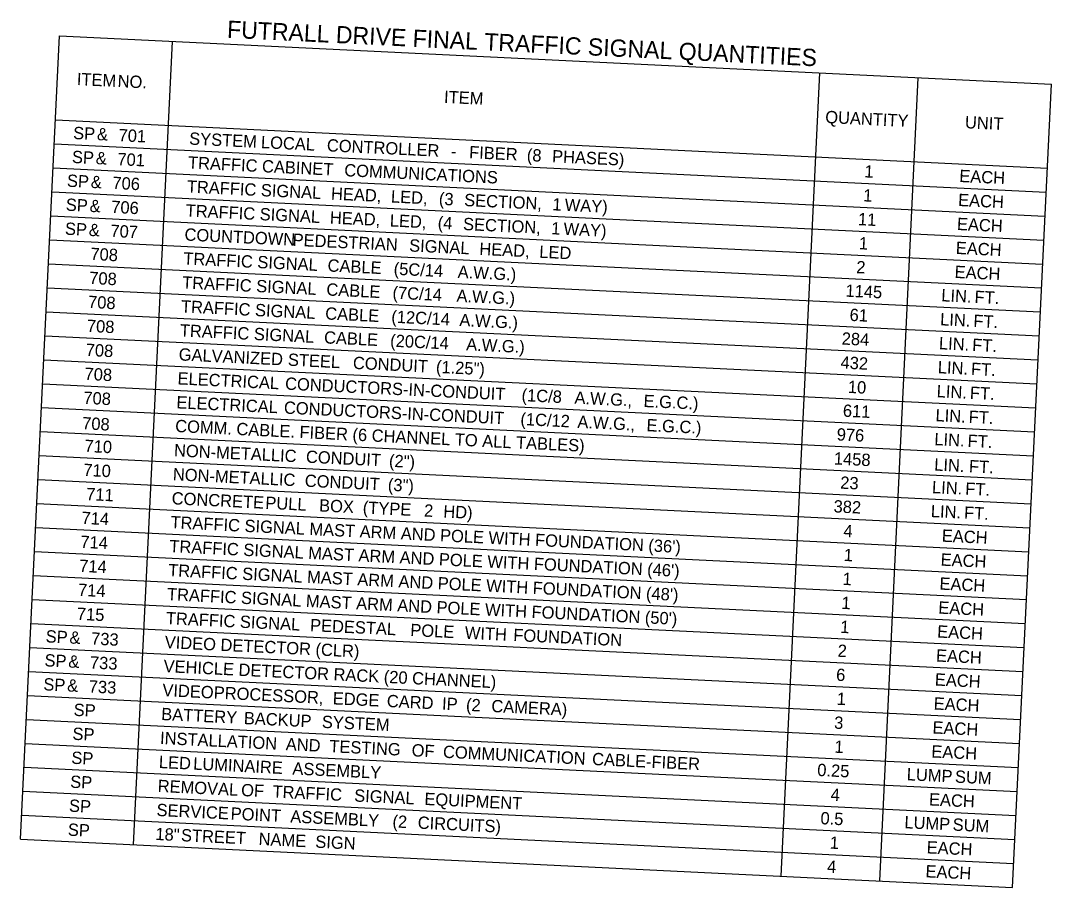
# Model space of a CAD drawing. Extents: x 661030 to 662601, y 642184 to 643065.
# Drawn here: x 661169.4 to 661372.2, y 642806.5 to 642977 of the extents above; entities that cross this region are included whole.
import ezdxf

# ---------------------------------------------------------------- set-up
doc = ezdxf.new("R2010")
doc.units = 0
doc.layers.add('R_Dimension', color=7, linetype='Continuous')

msp = doc.modelspace()

# ---------------------------------------------------------------- linework, layer by layer
at = {"layer": 'R_Dimension'}
for p, q in [((661169.39, 642815.93), (661177.07, 642973.95)), ((661177.07, 642973.95), (661372.16, 642964.47)), ((661191.59, 642814.85), (661199.24, 642972.87)), ((661319.02, 642808.66), (661326.64, 642966.68)), ((661338.39, 642807.72), (661345.98, 642965.74)), ((661364.48, 642806.45), (661372.16, 642964.47)), ((661176.26, 642957.44), (661371.36, 642947.96)), ((661176.04, 642952.72), (661371.13, 642943.25)), ((661175.81, 642948), (661370.9, 642938.53)), ((661175.58, 642943.28), (661370.67, 642933.81)), ((661175.35, 642938.57), (661370.44, 642929.09)), ((661175.12, 642933.85), (661370.21, 642924.38)), ((661174.89, 642929.13), (661369.98, 642919.66)), ((661174.66, 642924.42), (661369.75, 642914.94)), ((661174.43, 642919.7), (661369.52, 642910.23)), ((661174.2, 642914.98), (661369.29, 642905.51)), ((661173.97, 642910.27), (661369.06, 642900.79)), ((661173.97, 642910.27), (661369.06, 642900.79)), ((661173.74, 642905.55), (661368.84, 642896.08)), ((661173.52, 642900.83), (661368.61, 642891.36)), ((661173.29, 642896.11), (661368.38, 642886.64)), ((661173.06, 642891.4), (661368.15, 642881.92)), ((661172.83, 642886.68), (661367.92, 642877.21)), ((661172.6, 642881.96), (661367.69, 642872.49)), ((661172.37, 642877.25), (661367.46, 642867.77)), ((661172.14, 642872.53), (661367.23, 642863.06)), ((661171.91, 642867.81), (661367, 642858.34)), ((661171.68, 642863.1), (661366.77, 642853.62)), ((661171.45, 642858.38), (661366.55, 642848.9)), ((661171.23, 642853.66), (661366.32, 642844.19)), ((661171, 642848.94), (661366.09, 642839.47)), ((661170.77, 642844.23), (661365.86, 642834.75)), ((661170.54, 642839.51), (661365.63, 642830.04)), ((661170.54, 642839.51), (661365.63, 642830.04)), ((661170.31, 642834.79), (661365.4, 642825.32)), ((661170.08, 642830.08), (661365.17, 642820.6)), ((661169.85, 642825.36), (661364.94, 642815.89)), ((661169.62, 642820.64), (661364.71, 642811.17)), ((661169.39, 642815.93), (661364.48, 642806.45)), ((661169.39, 642815.93), (661364.48, 642806.45))]:
    msp.add_line(p, q, dxfattribs=at)

# ---------------------------------------------------------------- texts
for s, height, p in [('FUTRALL DRIVE FINAL TRAFFIC SIGNAL QUANTITIES', 3.3906, (661209.95, 642973.61)), ('ITEM', 2.422, (661180.41, 642964.3)), (' NO.', 2.422, (661187.53, 642963.95)), ('ITEM', 2.422, (661252.64, 642960.79)), ('QUANTITY', 2.422, (661327.63, 642956.84)), ('UNIT', 2.422, (661355.11, 642955.81)), ('SP', 2.422, (661179.68, 642953.69)), (' &', 2.422, (661183.47, 642953.51)), (' 701', 2.422, (661187.72, 642953.3)), ('SYSTEM', 2.422, (661202.51, 642952.59)), (' LOCAL', 2.422, (661215.73, 642951.94)), (' CONTROLLER', 2.4218, (661228.7, 642951.31)), ('SP', 2.422, (661179.45, 642948.98)), (' &', 2.422, (661183.24, 642948.79)), (' 701', 2.422, (661187.49, 642948.59)), (' -', 2.422, (661253.08, 642950.13)), (' FIBER', 2.422, (661256.68, 642949.95)), (' (8', 2.422, (661268.03, 642949.4)), (' PHASES)', 2.422, (661273, 642949.16)), ('TRAFFIC', 2.422, (661202.28, 642947.87)), (' CABINET', 2.422, (661215.93, 642947.2)), (' COMMUNICATIONS', 2.4218, (661232.12, 642946.42)), ('SP', 2.422, (661178.47, 642944.3)), ('1', 2.42, (661335.33, 642946.14)), ('EACH', 2.422, (661354, 642945.23)), (' &', 2.422, (661182.26, 642944.11)), (' 706', 2.422, (661186.51, 642943.91)), ('TRAFFIC', 2.422, (661202.05, 642943.15)), (' SIGNAL', 2.422, (661215.71, 642942.49)), (' HEAD,', 2.422, (661229.51, 642941.82)), (' LED,', 2.422, (661241.3, 642941.24)), (' (3', 2.422, (661250.73, 642940.79)), (' SECTION,', 2.422, (661255.7, 642940.55)), ('1', 2.42, (661335.1, 642941.42)), ('EACH', 2.422, (661353.77, 642940.51)), ('SP', 2.422, (661178.24, 642939.58)), (' &', 2.422, (661182.03, 642939.39)), (' 706', 2.422, (661186.28, 642939.19)), ('TRAFFIC', 2.422, (661201.82, 642938.43)), (' 1', 2.422, (661273.06, 642939.7)), (' WAY)', 2.422, (661275.48, 642939.59)), (' SIGNAL', 2.422, (661215.48, 642937.77)), (' HEAD,', 2.422, (661229.29, 642937.1)), (' LED,', 2.422, (661241.08, 642936.53)), ('11', 2.422, (661334.07, 642936.74)), ('SP', 2.422, (661178.08, 642934.86)), (' &', 2.422, (661181.87, 642934.67)), (' 707', 2.422, (661186.12, 642934.47)), (' (4', 2.422, (661250.5, 642936.07)), (' SECTION,', 2.422, (661255.48, 642935.83)), (' 1', 2.422, (661272.83, 642934.99)), (' WAY)', 2.422, (661275.25, 642934.87)), ('EACH', 2.422, (661353.54, 642935.79)), ('COUNTDOWN', 2.422, (661201.59, 642933.72)), (' PEDESTRIAN', 2.4218, (661221.95, 642932.73)), (' SIGNAL', 2.422, (661244.88, 642931.61)), (' HEAD,', 2.422, (661258.69, 642930.94)), (' LED', 2.422, (661270.48, 642930.37)), ('1', 2.42, (661334.25, 642932)), ('EACH', 2.422, (661353.31, 642931.08)), ('708', 2.422, (661183.08, 642929.89)), ('TRAFFIC', 2.422, (661201.36, 642929)), (' SIGNAL', 2.422, (661215.02, 642928.34)), (' CABLE', 2.422, (661228.83, 642927.67)), (' (5C/14', 2.422, (661241.84, 642927.03)), (' A.W.G.)', 2.422, (661254.43, 642926.42)), ('2', 2.42, (661333.73, 642927.3)), ('EACH', 2.422, (661353.08, 642926.36)), ('708', 2.422, (661182.85, 642925.17)), ('TRAFFIC', 2.422, (661201.13, 642924.28)), (' SIGNAL', 2.422, (661214.79, 642923.62)), (' CABLE', 2.422, (661228.6, 642922.95)), (' (7C/14', 2.422, (661241.61, 642922.32)), ('1145', 2.422, (661331.62, 642922.67)), ('708', 2.422, (661182.62, 642920.45)), (' A.W.G.)', 2.422, (661254.2, 642921.71)), ('LIN.', 2.422, (661350.46, 642921.76)), (' FT.', 2.422, (661356.1, 642921.49)), ('TRAFFIC', 2.422, (661200.9, 642919.57)), (' SIGNAL', 2.422, (661214.56, 642918.9)), (' CABLE', 2.422, (661228.37, 642918.23)), ('61', 2.422, (661332.42, 642917.91)), (' (12C/14', 2.422, (661241.38, 642917.6)), (' A.W.G.)', 2.422, (661254.77, 642916.95)), ('LIN.', 2.422, (661350.23, 642917.04)), (' FT.', 2.422, (661355.87, 642916.77)), ('708', 2.422, (661182.39, 642915.74)), ('TRAFFIC', 2.422, (661200.67, 642914.85)), (' SIGNAL', 2.422, (661214.33, 642914.19)), (' CABLE', 2.422, (661228.14, 642913.52)), (' (20C/14', 2.422, (661241.15, 642912.88)), (' A.W.G.)', 2.422, (661256.1, 642912.16)), ('284', 2.422, (661330.87, 642913.25)), ('LIN.', 2.422, (661350, 642912.33)), (' FT.', 2.422, (661355.64, 642912.05)), ('708', 2.422, (661182.16, 642911.02)), ('GALVANIZED', 2.422, (661200.45, 642910.13)), (' STEEL', 2.422, (661221.03, 642909.13)), (' CONDUIT', 2.422, (661233.82, 642908.51)), (' (1.25")', 2.422, (661250.16, 642907.72)), ('432', 2.422, (661330.64, 642908.54)), ('708', 2.422, (661181.93, 642906.3)), ('LIN.', 2.422, (661349.77, 642907.61)), (' FT.', 2.422, (661355.41, 642907.33)), ('ELECTRICAL', 2.422, (661200.22, 642905.41)), (' CONDUCTORS-IN-CONDUIT', 2.4218, (661220.48, 642904.43)), ('10', 2.422, (661332.08, 642903.74)), (' (1C/8', 2.422, (661267, 642902.17)), ('LIN.', 2.422, (661349.55, 642902.89)), (' FT.', 2.422, (661355.18, 642902.62)), ('708', 2.422, (661181.7, 642901.59)), ('ELECTRICAL', 2.422, (661199.99, 642900.7)), (' CONDUCTORS-IN-CONDUIT', 2.4218, (661220.25, 642899.71)), (' A.W.G.,', 2.422, (661277.41, 642901.67)), (' E.G.C.)', 2.422, (661290.99, 642901.01)), ('611', 2.422, (661331.1, 642899.06)), ('LIN.', 2.422, (661349.32, 642898.17)), (' FT.', 2.422, (661354.95, 642897.9)), ('708', 2.422, (661181.46, 642896.58)), ('COMM. CABLE. FIBER (6 CHANNEL TO ALL TABLES)', 2.4218, (661199.76, 642896.05)), (' (1C/12', 2.422, (661266.77, 642897.46)), (' A.W.G.,', 2.422, (661277.98, 642896.91)), (' E.G.C.)', 2.422, (661291.57, 642896.25)), ('976', 2.422, (661329.89, 642894.39)), ('710', 2.422, (661181.92, 642892.12)), ('LIN.', 2.422, (661349.09, 642893.46)), (' FT.', 2.422, (661354.73, 642893.18)), ('NON-METALLIC', 2.4218, (661199.53, 642891.26)), (' CONDUIT', 2.422, (661224.58, 642890.05)), ('1458', 2.422, (661329.33, 642889.66)), (' (2")', 2.422, (661240.92, 642889.25)), ('LIN. FT.', 2.422, (661349.07, 642888.46)), ('710', 2.422, (661181.69, 642887.4)), ('NON-METALLIC', 2.4218, (661199.3, 642886.55)), (' CONDUIT', 2.422, (661224.35, 642885.33)), (' (3")', 2.422, (661240.69, 642884.54)), ('23', 2.422, (661330.58, 642884.9)), ('LIN.', 2.422, (661348.63, 642884.02)), (' FT.', 2.422, (661354.27, 642883.75)), ('711', 2.422, (661182.25, 642882.65)), ('CONCRETE', 2.422, (661199.07, 642881.83)), (' PULL', 2.422, (661216.59, 642880.98)), (' BOX', 2.422, (661227.17, 642880.47)), (' (TYPE', 2.422, (661235.76, 642880.05)), (' 2', 2.422, (661247.81, 642879.46)), ('382', 2.422, (661329.27, 642880.24)), ('714', 2.422, (661181.34, 642877.96)), (' HD)', 2.422, (661251.6, 642879.28)), ('LIN.', 2.422, (661348.4, 642879.31)), (' FT.', 2.422, (661354.04, 642879.03)), ("TRAFFIC SIGNAL MAST ARM AND POLE WITH FOUNDATION (36')", 2.4218, (661198.84, 642877.11)), ('4', 2.42, (661331.21, 642875.41)), ('EACH', 2.422, (661350.56, 642874.47)), ('714', 2.422, (661181.11, 642873.25)), ("TRAFFIC SIGNAL MAST ARM AND POLE WITH FOUNDATION (46')", 2.4218, (661198.61, 642872.4)), ('1', 2.42, (661331.27, 642870.68)), ('EACH', 2.422, (661350.33, 642869.76)), ('714', 2.422, (661180.88, 642868.53)), ("TRAFFIC SIGNAL MAST ARM AND POLE WITH FOUNDATION (48')", 2.4218, (661198.38, 642867.68)), ('1', 2.42, (661331.04, 642865.97)), ('714', 2.422, (661180.65, 642863.81)), ('EACH', 2.422, (661350.1, 642865.04)), ("TRAFFIC SIGNAL MAST ARM AND POLE WITH FOUNDATION (50')", 2.4218, (661198.15, 642862.96)), ('1', 2.42, (661330.81, 642861.25)), ('715', 2.422, (661180.42, 642859.09)), ('EACH', 2.422, (661349.87, 642860.32)), ('TRAFFIC', 2.422, (661197.93, 642858.24)), (' SIGNAL', 2.422, (661211.58, 642857.58)), (' PEDESTAL', 2.422, (661225.39, 642856.91)), (' POLE', 2.422, (661245.11, 642855.95)), (' WITH', 2.422, (661255.83, 642855.43)), ('1', 2.42, (661330.58, 642856.53)), ('EACH', 2.422, (661349.65, 642855.61)), ('SP', 2.422, (661174.28, 642854.66)), (' &', 2.422, (661178.07, 642854.48)), (' 733', 2.422, (661182.32, 642854.27)), ('VIDEO DETECTOR (CLR)', 2.4218, (661197.7, 642853.53)), (' FOUNDATION', 2.4218, (661265.37, 642854.97)), ('2', 2.42, (661330.07, 642851.83)), ('SP', 2.422, (661174.05, 642849.95)), (' &', 2.422, (661177.84, 642849.76)), (' 733', 2.422, (661182.09, 642849.56)), ('EACH', 2.422, (661349.42, 642850.89)), ('VEHICLE DETECTOR RACK (20 CHANNEL)', 2.4218, (661197.47, 642848.81)), ('6', 2.42, (661329.77, 642847.11)), ('SP', 2.422, (661173.82, 642845.23)), (' &', 2.422, (661177.61, 642845.05)), ('EACH', 2.422, (661349.19, 642846.17)), (' 733', 2.422, (661181.86, 642844.84)), ('VIDEO', 2.422, (661197.24, 642844.09)), (' PROCESSOR,', 2.4218, (661206.44, 642843.65)), (' EDGE', 2.422, (661229.85, 642842.51)), (' CARD', 2.422, (661240.49, 642841.99)), (' IP', 2.422, (661251.35, 642841.47)), (' (2', 2.422, (661256.07, 642841.24)), (' CAMERA)', 2.422, (661261.05, 642841)), ('1', 2.42, (661329.89, 642842.38)), ('EACH', 2.422, (661348.96, 642841.45)), ('SP', 2.422, (661179.78, 642840.21)), ('BATTERY', 2.422, (661197.01, 642839.38)), (' BACKUP', 2.422, (661212.36, 642838.63)), (' SYSTEM', 2.422, (661227.71, 642837.89)), ('3', 2.42, (661329.38, 642837.68)), ('SP', 2.422, (661179.55, 642835.5)), ('EACH', 2.422, (661348.73, 642836.74)), ('INSTALLATION', 2.4218, (661196.78, 642834.66)), (' AND', 2.422, (661220.61, 642833.5)), (' TESTING', 2.422, (661229.18, 642833.09)), ('1', 2.42, (661329.44, 642832.95)), ('SP', 2.422, (661179.33, 642830.78)), (' OF', 2.422, (661245.37, 642832.3)), (' COMMUNICATION', 2.4218, (661251.54, 642832)), ('EACH', 2.422, (661348.5, 642832.02)), ('LED', 2.422, (661196.55, 642829.94)), (' LUMINAIRE', 2.422, (661202.4, 642829.66)), (' CABLE-FIBER', 2.4218, (661280.87, 642830.58)), (' ASSEMBLY', 2.422, (661221.92, 642828.71)), ('0.25', 2.422, (661326.06, 642828.38)), ('LUMP', 2.422, (661343.66, 642827.53)), (' SUM', 2.422, (661352.25, 642827.11)), ('SP', 2.422, (661179.1, 642826.06)), ('REMOVAL', 2.422, (661196.32, 642825.23)), (' OF', 2.422, (661211.83, 642824.47)), (' TRAFFIC', 2.422, (661218, 642824.17)), (' SIGNAL', 2.422, (661234.07, 642823.39)), (' EQUIPMENT', 2.422, (661247.88, 642822.72)), ('4', 2.42, (661328.69, 642823.53)), ('SP', 2.422, (661178.87, 642821.35)), ('EACH', 2.422, (661348.04, 642822.59)), ('SERVICE', 2.422, (661196.09, 642820.51)), (' POINT', 2.422, (661209.77, 642819.84)), (' ASSEMBLY', 2.422, (661221.5, 642819.27)), ('0.5', 2.422, (661326.69, 642818.89)), ('SP', 2.422, (661178.64, 642816.63)), (' (2', 2.422, (661241.6, 642818.3)), (' CIRCUITS)', 2.422, (661246.57, 642818.06)), ('LUMP', 2.422, (661343.2, 642818.09)), (' SUM', 2.422, (661351.79, 642817.68)), ('18"', 2.422, (661195.86, 642815.79)), (' STREET', 2.422, (661200, 642815.59)), (' NAME', 2.422, (661215.27, 642814.85)), (' SIGN', 2.422, (661226.42, 642814.31)), ('1', 2.42, (661328.52, 642814.08)), ('EACH', 2.422, (661347.58, 642813.15)), ('4', 2.42, (661328, 642809.37)), ('EACH', 2.422, (661347.35, 642808.44))]:
    msp.add_text(s, height=height, rotation=357.2199, dxfattribs=at).set_placement(p)

doc.saveas('drawing.dxf')
